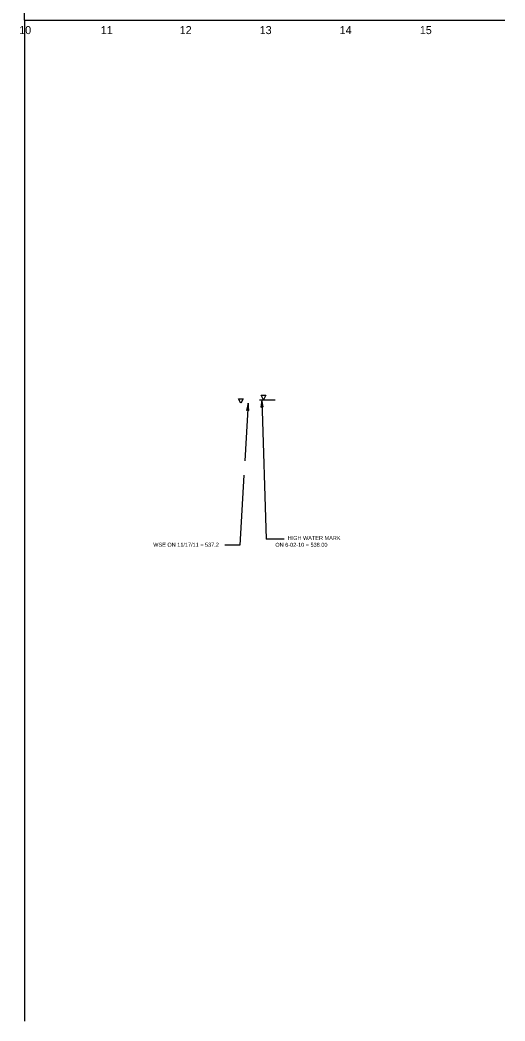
# Model space of a CAD drawing. Extents: x 1736530 to 1739201, y 695175 to 699135.
# Drawn here: x 1736607 to 1737212, y 696635 to 697885 of the extents above; entities that cross this region are included whole.
import ezdxf

# ---------------------------------------------------------------- set-up
doc = ezdxf.new("R2010")
doc.units = 0
for name, color, linetype in [('Default', 7, 'Continuous'), ('Exist Profile Cell', 7, 'Continuous'), ('Exist Vertical Profile Horizontal Axis Label Major', 7, 'Continuous'), ('Old_Level_5', 7, 'Continuous'), ('Prop Terminator CELL', 7, 'Continuous'), ('Prop VPI Label', 7, 'Continuous')]:
    doc.layers.add(name, color=color, linetype=linetype)

msp = doc.modelspace()

# ---------------------------------------------------------------- linework, layer by layer
at = {"layer": 'Default'}
msp.add_line((1736905.8, 697410.9), (1736925.1, 697410.9), dxfattribs=at)
at = {"layer": 'Exist Profile Cell'}
for q in [(1736612.1, 699135.1), (1737212.1, 697885.1), (1736612.1, 696635.1)]:
    msp.add_line((1736612.1, 697885.1), q, dxfattribs=at)
at = {"layer": 'Old_Level_5'}
for points in [[(1736882.3, 697406.7), (1736879.5, 697412.3), (1736885.1, 697412.3)], [(1736910.7, 697410.9), (1736907.9, 697416.5), (1736913.5, 697416.5)]]:
    msp.add_lwpolyline(points, close=True, dxfattribs=at)
at = {"layer": 'Prop Terminator CELL'}
for points in [[(1736892.3, 697397.6), (1736891.3, 697406.7), (1736889.2, 697397.7), (1736890.8, 697398.8)], [(1736910.4, 697402), (1736908.6, 697410.9), (1736907.3, 697401.8), (1736908.9, 697403)]]:
    msp.add_lwpolyline(points, close=True, dxfattribs=at)
at = {"layer": 'Prop VPI Label'}
for p, q in [((1736891.3, 697406.7), (1736887.2, 697334.6)), ((1736908.6, 697410.9), (1736914.1, 697236.7)), ((1736886.2, 697316.6), (1736881.2, 697229.5)), ((1736936.4, 697236.7), (1736914.1, 697236.7)), ((1736881.2, 697229.5), (1736862.2, 697229.5))]:
    msp.add_line(p, q, dxfattribs=at)

# ---------------------------------------------------------------- texts
at = {"layer": 'Default'}
for s, p in [('WSE ON 11/17/11 = 537.2', (1736773, 697227.4)), ('ON 6-02-10 = 538.00', (1736925.4, 697227.3)), ('HIGH WATER MARK', (1736940.8, 697235.8))]:
    msp.add_text(s, height=5, dxfattribs=at).set_placement(p)
at = {"layer": 'Exist Vertical Profile Horizontal Axis Label Major'}
for s, p in [('10', (1736605.7, 697867.6)), ('11', (1736707.5, 697867.6)), ('12', (1736806, 697867.6)), ('13', (1736905.9, 697867.6)), ('14', (1737005.7, 697867.6)), ('15', (1737105.8, 697867.6))]:
    msp.add_text(s, height=10, dxfattribs=at).set_placement(p)

doc.saveas('drawing.dxf')
